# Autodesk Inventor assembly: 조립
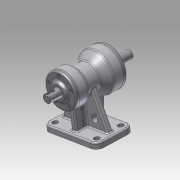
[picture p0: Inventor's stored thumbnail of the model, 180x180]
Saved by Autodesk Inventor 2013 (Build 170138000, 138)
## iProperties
Created: 2015-08
Part Number: 조립
Document SubType Name: Assembly
Designer: dgall
Author: dgall
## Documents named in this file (10)
- C:\Users\dgall\Desktop\450805V1029\조립.iam
- C:\Users\dgall\Desktop\450805V1029\M4x0.5.ipt
- C:\Users\dgall\Desktop\450805V1029\뒤커버.ipt
- C:\Users\dgall\Desktop\450805V1029\베어링 6203.ipt
- C:\Users\dgall\Desktop\450805V1029\베어링 6205.ipt
- C:\Users\dgall\Desktop\450805V1029\본체.ipt
- C:\Users\dgall\Desktop\450805V1029\앞커버.ipt
- C:\Users\dgall\Desktop\450805V1029\오일실 .ipt
- 오일실 .ipt
- C:\Users\dgall\Desktop\450805V1029\축.ipt
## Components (10 placed, 1 different names)
1. M4x0.5:1
2. M4x0.5:3
3. M4x0.5:4
4. M4x0.5:5
5. M4x0.5:6
6. M4x0.5:2
7. M4x0.5:7
8. M4x0.5:8
9. M4x0.5:9
10. M4x0.5:10
